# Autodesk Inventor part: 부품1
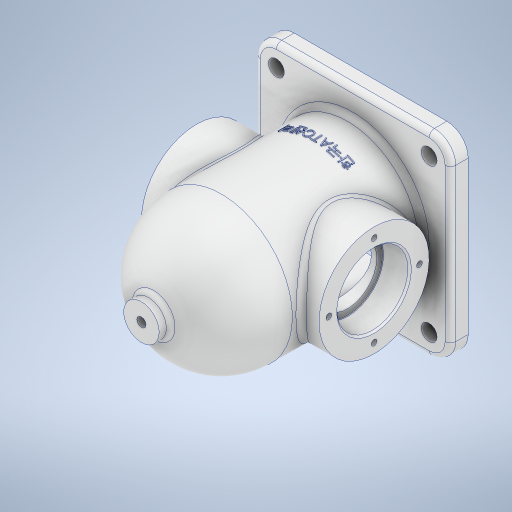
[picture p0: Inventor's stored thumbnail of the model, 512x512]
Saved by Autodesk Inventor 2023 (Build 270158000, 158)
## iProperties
Created: 2025-04
Part Number: 부품1
Material: 알루미늄 6061
Document SubType Name: Modeling
Designer: Admin
Density: 2.7 g/cm^3
Appearance: 알루미늄 - 평지
Mass: 1126.2 g
Surface Area: 808.366 cm^2
Volume: 417.112 cm^3
Author: Admin
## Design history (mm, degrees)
sketch "스케치1"
  geometry: L1 (-77, 0)-(77, 0) reference; L2 (0, -77)-(0, 77) reference; L3 (-55, -55)-(55, -55); L4 (55, -55)-(55, 55); L5 (55, 55)-(-55, 55); L6 (-55, 55)-(-55, -55); L7 (-55, -55)-(55, 55); L8 (55, -55)-(-55, 55); 1 further point
  constraints: 12 end point, 2 midpoint, 2 parallel, 1 perpendicular, 1 other
  dimensions: "d4" = 110 distance of L3.start L3.end; "d5" = 110 distance of L4.end L3.end
extrude "돌출1" new body sketch "스케치1" distance "d6" = 10; taper "d7" = 0 deg
sketch "스케치2"
  geometry: L1 (-77, 0)-(77, 0) reference; L2 (0, -77)-(0, 77) reference; C1 r 40 at (0, 0); 1 further point
  constraints: 1 centre point, 1 coincident
  dimensions: "d8" = 80 diameter of C1
extrude "돌출2" join sketch "스케치2" distance "d9" = 74; taper "d10" = 0 deg
sketch "스케치3"
  geometry: L1 (77, 0)-(-77, 0) reference; L2 (0, -24.8)-(0, 148.8) reference; L3 (-55, 0)-(-55, 10) reference; L4 (-55, 10)-(-40, 10) reference; L5 (-40, 10)-(-40, 84) reference; L6 (-40, 84)-(40, 84) reference; L7 (40, 84)-(40, 10) reference; L8 (40, 10)-(55, 10) reference; L9 (55, 10)-(55, 0) reference; L10 (55, 0)-(-55, 0) reference; L11 (40, 84)-(-40, 84) reference; A1 r 40 centre (0, 84) between (40, 84) and (-40, 84); 1 further point
  constraints: 2 point on circle, 1 centre point, 1 midpoint
revolve "회전1" sketch "스케치3" stored, may be unused: angle "d11" = 90 deg
node "작업 평면1"
sketch "스케치4"
  geometry: L1 (0, -15.8)-(0, 94.8) reference; L2 (-55, 0)-(55, 0) reference; C1 r 31 at (0, 48); 1 further point
  constraints: 1 centre point, 1 point on line
  dimensions: "d13" = 62 diameter of C1; "d14" = 48 distance from line of L2 C1.centre
extrude "돌출3" join sketch "스케치4" stored distance "d15" = 84; taper "d16" = 0 deg
sketch "스케치6"
  geometry: L1 (72.8, 0)-(-100.8, 0) reference; L2 (48, -55)-(48, 55) reference; C1 r 20 at (0, 0); 1 further point
  constraints: 1 centre point, 1 point on line
  dimensions: "d22" = 40 diameter of C1; "d23" = 48 distance from line of L2 C1.centre
extrude "돌출5" cut sketch "스케치6" distance "d24" = 15; taper "d25" = 0 deg
node "스케치7"
sketch "스케치8"
  geometry: L1 (72.8, 0)-(-100.8, 0) reference; L2 (48, -55)-(48, 55) reference; C1 r 16.5 at (0, 0); 1 further point
  constraints: 1 centre point, 1 point on line
  dimensions: "d26" = 33 diameter of C1; "d27" = 48 distance from line of L2 C1.centre
extrude "돌출6" cut sketch "스케치8" extent not by distance; stored distance "d28" = 0; taper "d29" = 0 deg
sketch "스케치10" dims "d35" = 51
  geometry: L1 (72.8, 0)-(-100.8, 0) reference; L2 (48, -55)-(48, 55) reference; 3 further points
  constraints: 2 point on line, 1 horizontal alignment, 2 other
  dimensions: "d36" = 48 distance from line of L2 point (0, 0)
hole "구멍1" sketch "스케치10" at (-25.5, 0) diameter "d37" = 3.242; stored, may be unused: countersink angle "d41" = 90 deg, drill point angle "d43" = 118 deg; dims "d38" = 8, "d39" = 4, "d40" = 2, "d42" = 10
node "작업 평면2"
sketch "스케치12"
  geometry: L1 (-19, 0)-(44, 0) reference; L2 (0, -14)-(0, 14) reference; C1 r 10 at (0, 0); 1 further point
  constraints: 1 centre point, 1 coincident
  dimensions: "d48" = 20 diameter of C1
extrude "돌출8" join sketch "스케치12" stored distance "d49" = 74; taper "d50" = 0 deg
sketch "스케치13"
  geometry: 2 further points
  constraints: 1 coincident
hole "구멍2" sketch "스케치13" at (0, 0) diameter "d51" = 5.1881; stored, may be unused: countersink angle "d55" = 90 deg, drill point angle "d57" = 118 deg; dims "d52" = 14, "d53" = 4, "d54" = 2, "d56" = 16
fillet "모깎기1" dims "d58" = 12
sketch "스케치14"
  geometry: L1 (-77.497, 0)-(79.982, 0) reference; L2 (0, -77.497)-(0, 79.982) reference; C1 r 4.5 at (43, 43); A1 r 12 centre (43, 43) between (55, 43) and (43, 55) reference; 1 further point
  constraints: 1 centre point, 1 coincident
  dimensions: "d59" = 9 diameter of C1
extrude "돌출9" cut sketch "스케치14" extent not by distance; stored distance "d60" = 0; taper "d61" = 0 deg
fillet "모깎기2" dims "d62" = 3
fillet "모깎기3" dims "d63" = 3
fillet "모깎기4" dims "d64" = 3
node "작업 평면3"
sketch "스케치15"
  geometry: L1 (-43, 0)-(43, 0) reference; 2 further points
  constraints: 1 other
  dimensions: "d66" = 30 distance from line of L1 point (0.297, 30)
feature "엠보싱1" sketch "스케치15" dims "d67" = 0.5, "d68" = 0
fillet "모깎기5" dims "d69" = 0.3
sketch "스케치18"
  geometry: L1 (32, 84)-(32, 0); L2 (-43, 0)-(43, 0) reference; L3 (77, 0)-(-77, 0) reference; L4 (0, -25.8)-(0, 154.8) reference; L5 (32, 0)-(0, 0); L6 (0, 0)-(0, 116); L7 (-2.594, 113)-(-2.594, 129) reference; A1 r 40 centre (0, 84) between (40, 84) and (-40, 84) reference; A2 r 32 centre (0, 84) between (32, 84) and (0, 116)
  constraints: 6 end point, 2 point on circle, 2 point on line, 1 centre point, 1 collinear, 1 parallel, 1 vertical
  dimensions: "d74" = 8 radial gap between concentric circles of A1 A2
revolve "회전2" sketch "스케치18" stored, may be unused: angle "d75" = 360 deg
chamfer "모따기1" distance "d76" = 1; stored, may be unused: second distance "d77" = 2, angle "d78" = 45 deg
node "솔리드1"
mirror "미러1"
mirror "미러2"
pattern_circular "원형 패턴1" dims angle "d45" = 360 deg
mirror "미러3"
mirror "미러4"
mirror "미러5"
node "절단 모서리 투영1"
feature "A9D066F2-1C7D-4E18-AEED-F7BC21143FA4" dims "d51" = 5.1881, "d52" = 14, "d53" = 4, "d54" = 2, "d55" = 90 deg, "d56" = 16, "d57" = 118 deg
other parameters: "d47" = 129
